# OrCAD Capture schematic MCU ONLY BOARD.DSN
size A
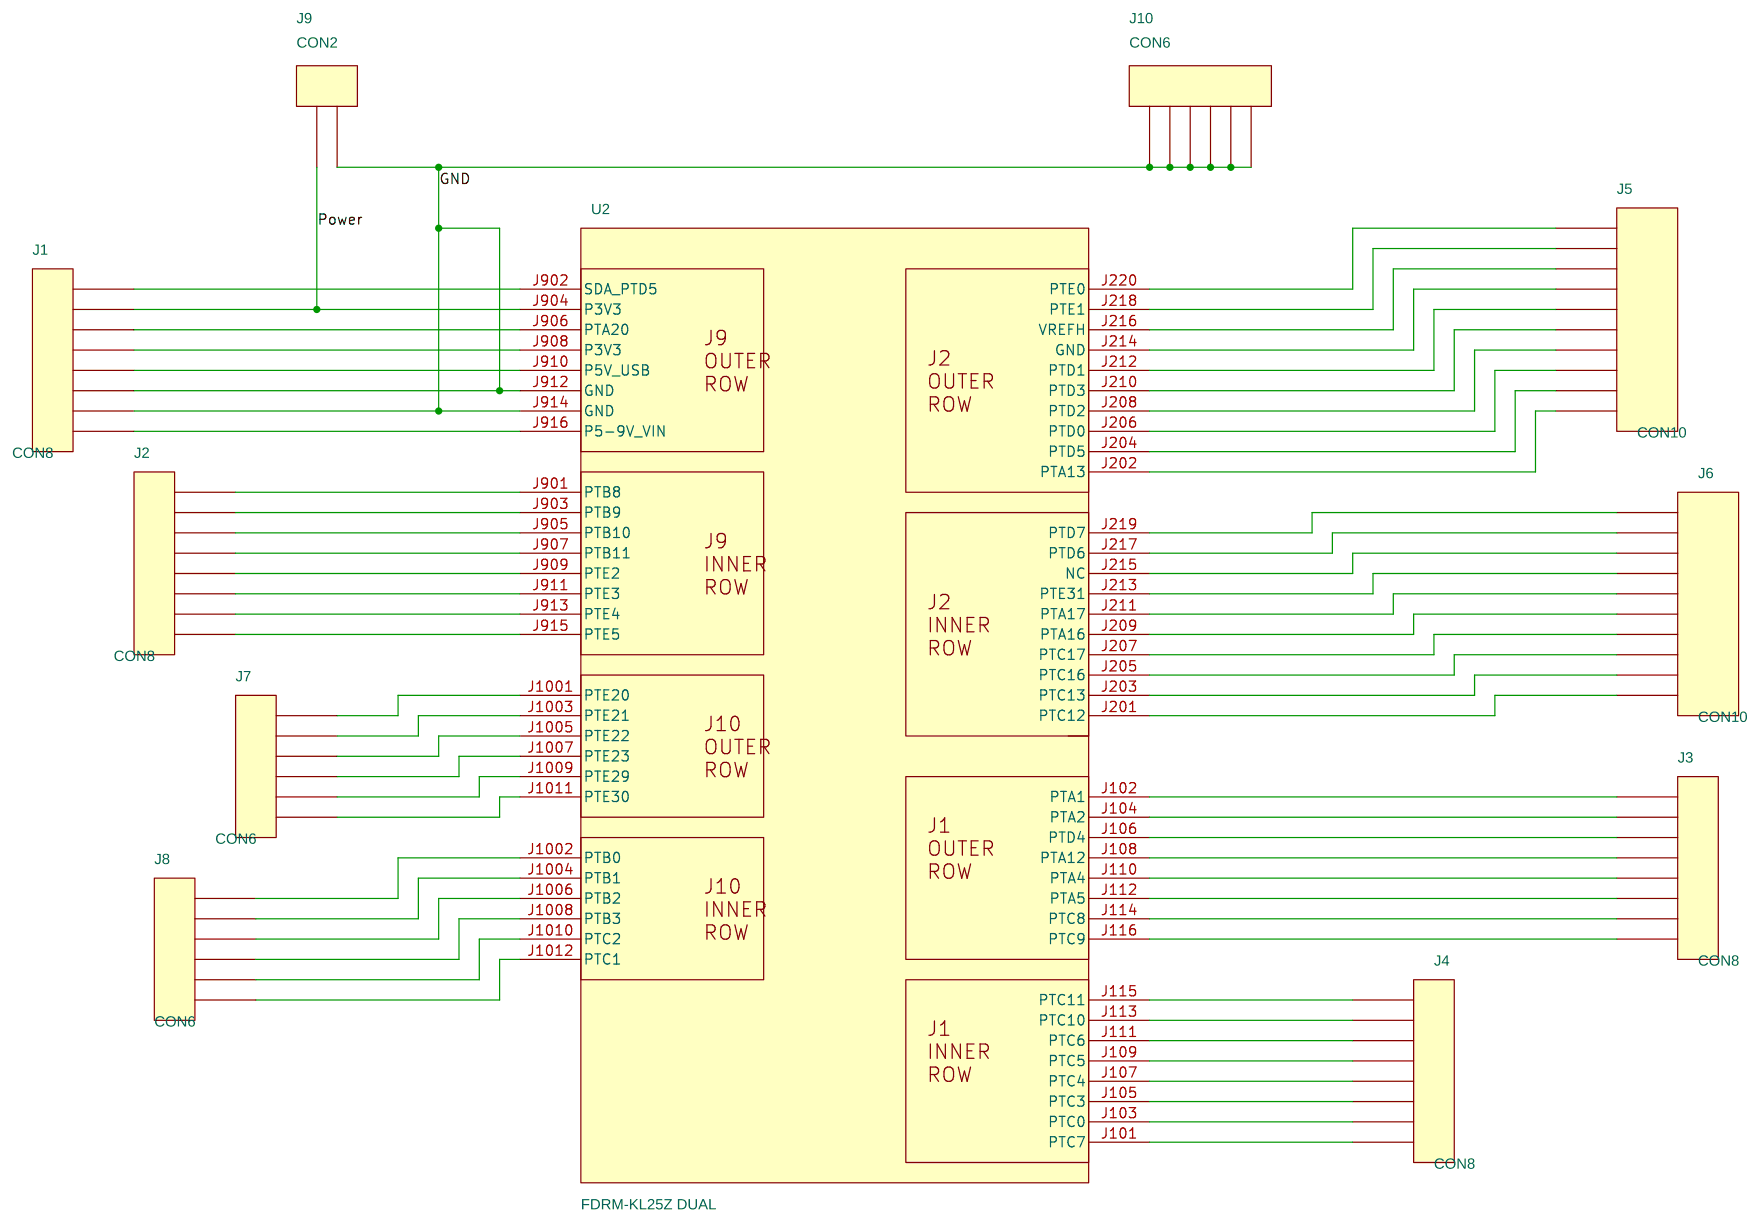
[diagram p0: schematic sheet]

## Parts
J1  CON8  [GU-MOLEX8]
J2  CON8  [GU-MOLEX8]
J3  CON8  [GU-MOLEX8]
J4  CON8  [GU-MOLEX8]
J5  CON10  [GU-MOLEX10]
J6  CON10  [GU-MOLEX10]
J7  CON6  [GU-MOLEX6]
J8  CON6  [GU-MOLEX6]
J9  CON2  [GU-MOLEX2]
J10  CON6  [GU-MOLEX6]
U2  FDRM-KL25Z DUAL  [gu-frdm-kl25z]

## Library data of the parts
J1-J4 = CON8
J5 J6 = CON10
J7 J8 J10 = CON6
J9 = CON2
U2 = FDRM-KL25Z_DUAL

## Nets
GND: J1.6 J1.7 J9.2 J10.1 J10.2 J10.3 J10.4 J10.5 J10.6 U2.J912(GND) U2.J914(GND)
Power: J1.2 J9.1 U2.J904(P3V3)
N00971: J1.1 U2.J902(SDA_PTD5)
N00975: J1.3 U2.J906(PTA20)
N00977: J1.4 U2.J908(P3V3)
N00979: J1.5 U2.J910(P5V_USB)
N00985: J1.8 U2.J916(P5-9V_VIN)
N01053: J2.1 U2.J901(PTB8)
N01055: J2.2 U2.J903(PTB9)
N01057: J2.3 U2.J905(PTB10)
N01059: J2.4 U2.J907(PTB11)
N01061: J2.5 U2.J909(PTE2)
N01063: J2.6 U2.J911(PTE3)
N01065: J2.7 U2.J913(PTE4)
N01067: J2.8 U2.J915(PTE5)
N01138: J7.1 U2.J1001(PTE20)
N01140: J7.2 U2.J1003(PTE21)
N01142: J7.3 U2.J1005(PTE22)
N01144: J7.4 U2.J1007(PTE23)
N01146: J7.5 U2.J1009(PTE29)
N01148: J7.6 U2.J1011(PTE30)
N01262: J8.1 U2.J1002(PTB0)
N01268: J8.2 U2.J1004(PTB1)
N01274: J8.3 U2.J1006(PTB2)
N01280: J8.4 U2.J1008(PTB3)
N01286: J8.5 U2.J1010(PTC2)
N01292: J8.6 U2.J1012(PTC1)
N01663: J6.1 U2.J219(PTD7)
N01669: J6.2 U2.J217(PTD6)
N01675: J6.3 U2.J215(NC)
N01681: J6.4 U2.J213(PTE31)
N01687: J6.5 U2.J211(PTA17)
N01693: J6.6 U2.J209(PTA16)
N01699: J6.7 U2.J207(PTC17)
N01705: J6.8 U2.J205(PTC16)
N01711: J6.9 U2.J203(PTC13)
N01717: J6.10 U2.J201(PTC12)
N01937: J3.1 U2.J102(PTA1)
N01939: J3.2 U2.J104(PTA2)
N01941: J3.3 U2.J106(PTD4)
N01943: J3.4 U2.J108(PTA12)
N01945: J3.5 U2.J110(PTA4)
N01947: J3.6 U2.J112(PTA5)
N01949: J3.7 U2.J114(PTC8)
N01951: J3.8 U2.J116(PTC9)
N03369: J5.1 U2.J220(PTE0)
N03375: J5.2 U2.J218(PTE1)
N03381: J5.3 U2.J216(VREFH)
N03387: J5.4 U2.J214(GND)
N03393: J5.5 U2.J212(PTD1)
N03399: J5.6 U2.J210(PTD3)
N03405: J5.7 U2.J208(PTD2)
N03411: J5.8 U2.J206(PTD0)
N03417: J5.9 U2.J204(PTD5)
N03423: J5.10 U2.J202(PTA13)
N04658: J4.1 U2.J115(PTC11)
N04660: J4.2 U2.J113(PTC10)
N04662: J4.3 U2.J111(PTC6)
N04664: J4.4 U2.J109(PTC5)
N04666: J4.5 U2.J107(PTC4)
N04668: J4.6 U2.J105(PTC3)
N04670: J4.7 U2.J103(PTC0)
N04672: J4.8 U2.J101(PTC7)
